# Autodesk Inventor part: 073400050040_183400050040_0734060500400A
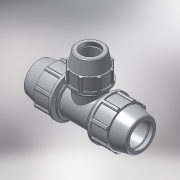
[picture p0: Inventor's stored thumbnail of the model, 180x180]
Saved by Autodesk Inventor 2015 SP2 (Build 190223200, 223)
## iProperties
Created: 2017-02
Part Number: 073400050040_183400050040_0734060500400A
Material: PVC-Piping
Description: PLASSON REDUCING TEE 50-40-50
Document SubType Name: Modeling
Designer: KIM
Mass: 92.6774 g
Surface Area: 199.44 cm^2
Volume: 66.1981 cm^3
Density: 1.4 g/cm^3
Appearance: Smooth - White
Author: Кирилл
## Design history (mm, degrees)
derived "07340.ipt"
feature "Solid1::07340.ipt"
feature "Solid2::07340.ipt"
tag "TaggingFeature1"
body "Solid1"
other parameters: "d4" = 9.83333, "d5" = 33.04, "d7" = 96, "d11" = 3.93333, "d13" = 120 deg, "d15" = 12 deg, "d16" = 83.52, "d18" = 2.5, "d19" = 35 deg, "d20" = 17.5 deg, "d21" = 89.28, "d23" = 0, "d25" = 360 deg, "d27" = 1.92, "d33" = 1, "d42" = 42.48, "d43" = 2.88, "d46" = 1.5, "d67" = 72, "d77" = 82, "d78" = 12 deg, "d79" = 114, "d80" = 120 deg, "d82" = 9.5, "d87" = 3.8, "d89" = 28.5, "d90" = 34.2, "d96" = 19.66667, "d98" = 76.26, "d99" = 35 deg, "d100" = 17.5 deg, "d102" = 0, "d103" = 1.64, "d107" = 360 deg, "d109" = 1.2, "d112" = 2, "d113" = 5.46667, "d114" = 0, "d117" = 236, "d118" = 71.34, "d126" = 45, "d127" = 93, "d131" = 4.56, "d132" = 36, "d133" = 82, "d135" = 0, "d138" = 4.72, "d143" = 0, "d148" = 61.5, "d168" = 45, "d170" = 0, "d173" = 0, "d175" = 0, "d176" = 5.46667, "d177" = 0, "E_" = 96, "A_" = 114, "l_" = 93, "E_1" = 82, "l_1" = 82, "H_" = 236
